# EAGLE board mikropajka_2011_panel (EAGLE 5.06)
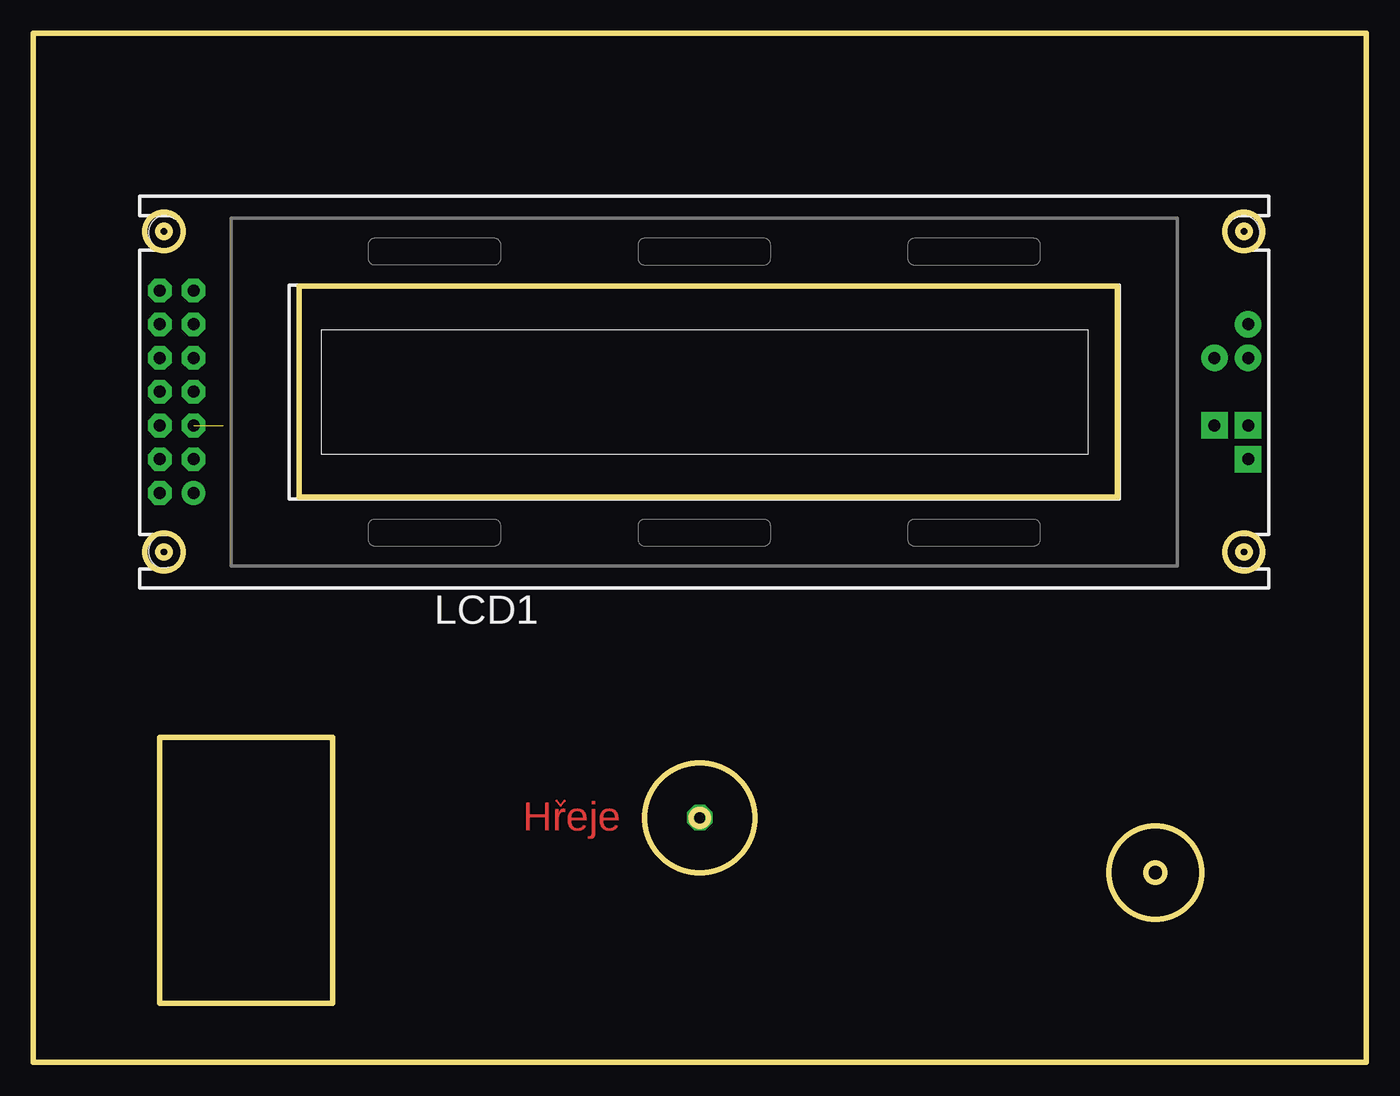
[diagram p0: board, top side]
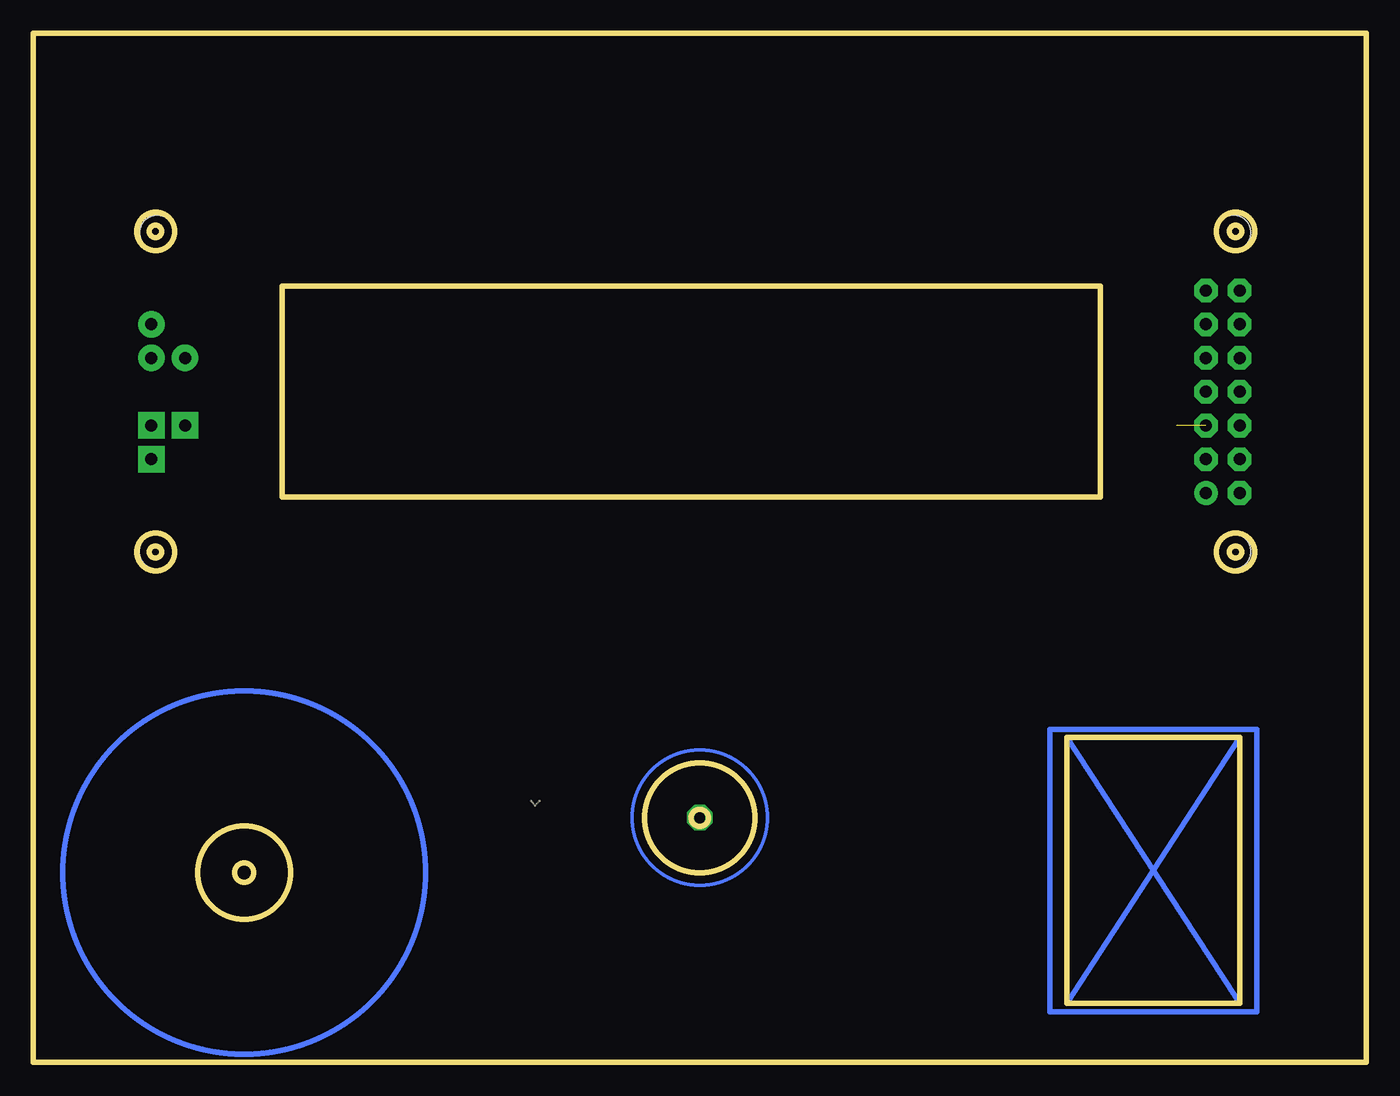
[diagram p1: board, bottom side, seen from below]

Size 100.33 x 77.47 mm. Coordinates in mm from the lower left corner, seen from the top.
Outline: 100.33,0 0,0 0,77.47 100.33,77.47 100.33,0
Outline: 20,58.42 20,42.55 81.6,42.55 81.6,58.42 20,58.42
Outline: 9.53,4.45 22.54,4.45 22.54,24.45 9.53,24.45 9.53,4.45
Outline: circle at 50.16,18.41 radius 4.13
Outline: circle at 84.45,14.29 radius 0.71
Outline: circle at 50.16,18.41 radius 0.64
Outline: circle at 9.84,62.55 radius 1.42
Outline: circle at 9.84,62.55 radius 0.45
Outline: circle at 9.84,38.42 radius 1.42
Outline: circle at 9.84,38.42 radius 0.45
Outline: circle at 91.12,62.55 radius 1.42
Outline: circle at 91.12,62.55 radius 0.45
Outline: circle at 91.12,38.42 radius 1.42
Outline: circle at 91.12,38.42 radius 0.45
Outline: circle at 84.45,14.29 radius 3.49
Copper layers (1*16): Top 0.035mm / dielectric 1.5mm / Bottom 0.035mm
Design rules "default": minimum track width 10mil, minimum drill 24mil, track to track 8mil, track to pad 8mil, pad to pad 8mil, via to via 8mil, smd to smd 8mil, copper to edge 40mil, drill to drill 8mil, minimum pad ring 10mil, minimum via ring 8mil, stop-mask expansion 4mil, vias tented up to drill 0mil, thermal gap 10mil
bRestrict: area 90.2,56.5 to 95.9,62.2; area 91.8,92.7 to 97.5,98.4; area 12.7,92.7 to 18.4,98.4

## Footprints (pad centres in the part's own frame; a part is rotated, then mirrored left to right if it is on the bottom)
PRC1602A = drill 0.9 pad 1.778 round: 1 -38.1,-7.62 | drill 0.9 pad 1.778 octagon: 2 -40.64,-7.62; 3 -38.1,-5.08; 4 -40.64,-5.08; 5 -38.1,-2.54; 6 -40.64,-2.54; 7 -38.1,0; 8 -40.64,0; 9 -38.1,2.54; 10 -40.64,2.54; 11 -38.1,5.08; 12 -40.64,5.08; 13 -38.1,7.62; 14 -40.64,7.62 | drill 0.9 pad 2 round: A 41.275,5.08; A1 41.275,2.54; A2 38.735,2.54 | drill 0.9 pad 2 square: K 41.275,-5.08; K1 41.275,-2.54; K2 38.735,-2.54 | hole 2.6: -40.172,11.976; -40.172,-12.026; 40.871,-12.026; 40.84,11.976

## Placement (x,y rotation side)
LCD1  PRC1602A  [PRC1602A]  50.16,50.48 0 top

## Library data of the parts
LCD1 = #PaJa_displeje

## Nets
+5V: LCD1.1 LCD1.A
DB4: LCD1.11
DB5: LCD1.12
DB6: LCD1.13
DB7: LCD1.14
E: LCD1.6
N$20: LCD1.K
RS: LCD1.4
S$7: LCD1.2 LCD1.5
VO: LCD1.3

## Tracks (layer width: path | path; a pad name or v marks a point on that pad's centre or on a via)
N$28  (via drill 0.81 pad 1.93)
  other vias: 50.16,18.41
S$1
  Bottom 0.406: 8.26,3.81 23.81,3.81 23.81,25.08 8.26,25.08 8.26,3.81
S$2
  Bottom 0.406: 9.53,4.45 22.54,24.45
S$3
  Bottom 0.406: 9.53,24.45 22.54,4.45
S$4
  Top 0.203: 39.37,19.68 39.69,19.37 | 39.69,19.37 | 39.69,19.37 40.01,19.68
S$7  (1 unrouted)
(copper drawn outside any net)
  shapes: Bottom circle x2

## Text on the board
Top: Hreje
bDocu: Nehreje
Kola: Stand-by
Popisy: mikro | k
Zapojeni: PaJ | a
